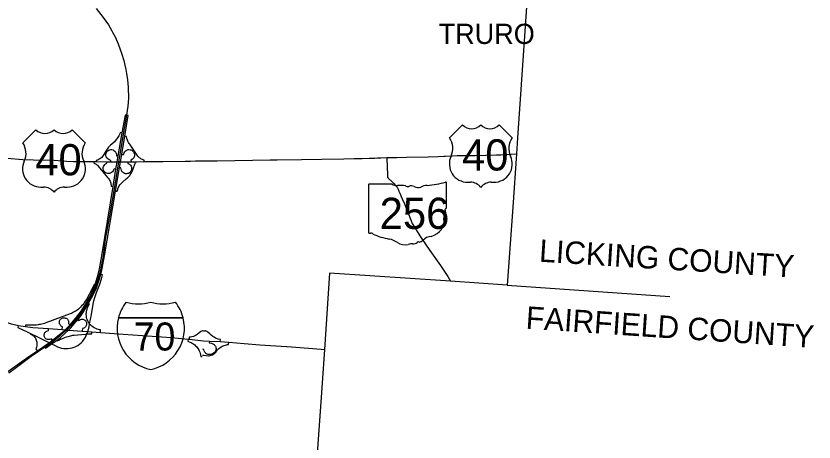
# Model space of a CAD drawing. Extents: x -1146 to -445, y -1283 to -822.
# Drawn here: x -786.6 to -697.7, y -1096.4 to -1048.9 of the extents above; entities that cross this region are included whole.
import ezdxf

# ---------------------------------------------------------------- set-up
doc = ezdxf.new("R2010")
doc.units = 0
for name, color, linetype in [('GM_X_Adjacent_County', 7, 'Continuous'), ('GM_X_Adjacent_County_Text', 7, 'Continuous'), ('GM_X_County', 7, 'Continuous'), ('GM_X_Interchange_Ramps', 7, 'Continuous'), ('GM_X_Interstate_Route', 7, 'Continuous'), ('GM_X_Interstate_Shield', 7, 'Continuous'), ('GM_X_State_Route', 7, 'Continuous'), ('GM_X_State_Shield', 7, 'Continuous'), ('GM_X_Township_Text', 7, 'Continuous'), ('GM_X_US_Route', 7, 'Continuous'), ('GM_X_US_Shield', 7, 'Continuous')]:
    doc.layers.add(name, color=color, linetype=linetype)

msp = doc.modelspace()

# ---------------------------------------------------------------- linework, layer by layer
at = {"layer": 'GM_X_Adjacent_County'}
msp.add_line((-731.874, -1078.923), (-713.764, -1080.18), dxfattribs=at)
at = {"layer": 'GM_X_County'}
msp.add_lwpolyline([(-722.786, -1003.387), (-723.025, -1007.4), (-723.916, -1019.919), (-723.932, -1020.299), (-724.826, -1035.597), (-725.049, -1038.96), (-725.51, -1045.915), (-729.553, -1045.554), (-729.679, -1047.366), (-730.581, -1060.332), (-730.732, -1062.497), (-730.857, -1064.3), (-731.27, -1070.236), (-731.413, -1072.292), (-731.874, -1078.923), (-738.201, -1078.491), (-751.672, -1077.572), (-752.243, -1086.092), (-752.566, -1090.897), (-753.436, -1103.447)], dxfattribs=at)
at = {"layer": 'GM_X_Interchange_Ramps'}
for points in [[(-774.284, -1059.994), (-774.439, -1059.969), (-774.786, -1061.933), (-775.242, -1064.513), (-775.362, -1065.189), (-775.49, -1065.978), (-775.805, -1067.922), (-777.062, -1075.666), (-777.33, -1077.117), (-777.534, -1078.031), (-777.805, -1078.876), (-777.93, -1079.239), (-778.251, -1079.987), (-778.835, -1081.021), (-779.33, -1081.793), (-779.991, -1082.661), (-780.581, -1083.362), (-780.665, -1083.461), (-781.112, -1083.913), (-781.367, -1084.17), (-782.298, -1084.92), (-782.503, -1085.083), (-782.853, -1085.362), (-782.864, -1085.37), (-784.195, -1086.275), (-785.164, -1086.934), (-787.48, -1088.581)], [(-783.374, -1085.85), (-783.3, -1085.951), (-782.615, -1085.478), (-782.329, -1085.281), (-782.009, -1085.06), (-781.629, -1084.755), (-781.096, -1084.295), (-780.73, -1083.942), (-780.464, -1083.685), (-779.903, -1083.025), (-779.713, -1082.782), (-779.342, -1082.309), (-778.714, -1081.34), (-778.5, -1080.957), (-778.304, -1080.606), (-778.007, -1080.071), (-777.672, -1079.337), (-777.353, -1078.448), (-777.14, -1077.724), (-777.003, -1077.052), (-776.733, -1075.67), (-775.493, -1068.432), (-775.046, -1065.819), (-774.938, -1065.189), (-774.937, -1065.183), (-774.801, -1064.35), (-774.468, -1062.312), (-774.095, -1060.023), (-774.284, -1059.994)], [(-774.786, -1061.933), (-774.968, -1061.904), (-775.036, -1062.069), (-775.092, -1062.19), (-775.148, -1062.296), (-775.205, -1062.396), (-775.269, -1062.496), (-775.343, -1062.602), (-775.418, -1062.701), (-775.502, -1062.801), (-775.55, -1062.855), (-775.622, -1062.93), (-775.915, -1063.2), (-776.052, -1063.32), (-776.163, -1063.429), (-776.265, -1063.541), (-776.346, -1063.64), (-776.431, -1063.755), (-776.508, -1063.87), (-776.574, -1063.981), (-776.798, -1064.378), (-776.865, -1064.485), (-776.944, -1064.587), (-777.035, -1064.683), (-777.146, -1064.778), (-777.239, -1064.843), (-777.322, -1064.891), (-777.415, -1064.937), (-777.518, -1064.976), (-777.643, -1065.013), (-777.647, -1065.151)], [(-772.304, -1065.152), (-772.308, -1064.992), (-772.408, -1064.962), (-772.508, -1064.925), (-772.601, -1064.882), (-772.685, -1064.834), (-772.767, -1064.78), (-772.844, -1064.721), (-772.916, -1064.657), (-772.976, -1064.596), (-773.028, -1064.536), (-773.921, -1063.217), (-773.992, -1063.116), (-774.053, -1063.015), (-774.092, -1062.941), (-774.13, -1062.858), (-774.167, -1062.765), (-774.2, -1062.669), (-774.229, -1062.56), (-774.271, -1062.342), (-774.468, -1062.312)], [(-776.014, -1065.178), (-776.01, -1065.018), (-776.191, -1064.95), (-776.35, -1064.859), (-776.485, -1064.715), (-776.544, -1064.573), (-776.567, -1064.449), (-776.564, -1064.329), (-776.533, -1064.201), (-776.491, -1064.112), (-776.415, -1064.007), (-776.339, -1063.938), (-776.243, -1063.877), (-776.142, -1063.838), (-776.024, -1063.817), (-775.899, -1063.821), (-775.761, -1063.858), (-775.67, -1063.904), (-775.575, -1063.976), (-775.501, -1064.062), (-775.449, -1064.15), (-775.414, -1064.241), (-775.397, -1064.321), (-775.379, -1064.492), (-775.242, -1064.513)], [(-774.801, -1064.35), (-774.627, -1064.377), (-774.574, -1064.253), (-774.48, -1064.074), (-774.422, -1064.002), (-774.324, -1063.918), (-774.243, -1063.871), (-774.157, -1063.838), (-774.079, -1063.82), (-773.999, -1063.813), (-773.883, -1063.822), (-773.77, -1063.853), (-773.694, -1063.889), (-773.627, -1063.932), (-773.556, -1063.995), (-773.494, -1064.071), (-773.45, -1064.144), (-773.414, -1064.236), (-773.393, -1064.328), (-773.388, -1064.417), (-773.397, -1064.516), (-773.429, -1064.63), (-773.478, -1064.727), (-773.547, -1064.818), (-773.61, -1064.876), (-773.777, -1064.991), (-773.771, -1065.173)], [(-777.922, -1065.146), (-777.926, -1065.307), (-777.794, -1065.367), (-777.715, -1065.411), (-777.654, -1065.45), (-777.588, -1065.5), (-777.514, -1065.563), (-777.438, -1065.643), (-776.377, -1066.917), (-776.289, -1067.028), (-776.222, -1067.129), (-776.161, -1067.236), (-776.112, -1067.338), (-776.072, -1067.439), (-776.036, -1067.548), (-776.008, -1067.657), (-775.989, -1067.757), (-775.973, -1067.893), (-775.805, -1067.922)], [(-775.49, -1065.978), (-775.643, -1065.955), (-775.774, -1066.185), (-775.85, -1066.275), (-775.932, -1066.356), (-776.044, -1066.428), (-776.164, -1066.47), (-776.288, -1066.485), (-776.408, -1066.475), (-776.532, -1066.435), (-776.635, -1066.377), (-776.724, -1066.297), (-776.793, -1066.205), (-776.846, -1066.09), (-776.873, -1065.969), (-776.87, -1065.817), (-776.836, -1065.694), (-776.777, -1065.581), (-776.695, -1065.484), (-776.606, -1065.415), (-776.474, -1065.343), (-776.47, -1065.171)], [(-775.493, -1068.432), (-775.309, -1068.464), (-775.257, -1068.271), (-775.224, -1068.174), (-775.187, -1068.08), (-775.138, -1067.976), (-775.075, -1067.865), (-775.003, -1067.754), (-774.937, -1067.667), (-774.844, -1067.56), (-774.733, -1067.452), (-774.679, -1067.405), (-774.3, -1067.082), (-774.209, -1067.006), (-774.128, -1066.932), (-774.055, -1066.859), (-773.989, -1066.785), (-773.921, -1066.703), (-773.852, -1066.609), (-773.791, -1066.518), (-773.732, -1066.42), (-773.607, -1066.172), (-773.52, -1065.947), (-773.363, -1065.434), (-773.329, -1065.346), (-773.275, -1065.276), (-773.192, -1065.219), (-773.194, -1065.165)], [(-774.124, -1065.178), (-774.119, -1065.353), (-773.928, -1065.452), (-773.841, -1065.54), (-773.768, -1065.649), (-773.721, -1065.772), (-773.704, -1065.883), (-773.708, -1065.998), (-773.746, -1066.138), (-773.803, -1066.248), (-773.882, -1066.342), (-773.958, -1066.404), (-774.066, -1066.463), (-774.166, -1066.494), (-774.274, -1066.508), (-774.38, -1066.501), (-774.501, -1066.47), (-774.614, -1066.413), (-774.7, -1066.344), (-774.758, -1066.28), (-774.81, -1066.2), (-774.843, -1066.127), (-774.876, -1065.996), (-774.898, -1065.84), (-775.046, -1065.819)], [(-786.324, -1083.405), (-786.378, -1083.656), (-785.347, -1084.128), (-784.972, -1084.305), (-784.257, -1084.641), (-783.082, -1085.25), (-782.853, -1085.362), (-782.73, -1085.422), (-782.615, -1085.478), (-782.22, -1085.67), (-781.962, -1085.8), (-781.733, -1085.885), (-781.508, -1085.945), (-781.252, -1085.986), (-781.008, -1086), (-780.808, -1085.993), (-780.547, -1085.958), (-780.313, -1085.903), (-780.107, -1085.833), (-779.91, -1085.747), (-779.711, -1085.637), (-779.513, -1085.501), (-779.33, -1085.348), (-779.174, -1085.189), (-778.992, -1084.96), (-778.854, -1084.74), (-778.759, -1084.551), (-778.683, -1084.365), (-778.633, -1084.246), (-778.581, -1084.097), (-778.576, -1084.083), (-778.506, -1083.845), (-778.443, -1083.561), (-778.382, -1083.247), (-778.175, -1082.182), (-777.983, -1081.038), (-777.897, -1080.663), (-777.812, -1080.3), (-777.619, -1079.733), (-777.256, -1078.803), (-777.064, -1078.215), (-776.943, -1077.778), (-777.14, -1077.724)], [(-777.805, -1078.876), (-777.887, -1078.846), (-778.175, -1079.466), (-778.432, -1079.979), (-778.699, -1080.46), (-778.945, -1080.835), (-779.029, -1080.953), (-779.151, -1081.109), (-779.271, -1081.246), (-779.397, -1081.376), (-779.518, -1081.49), (-779.628, -1081.584), (-779.773, -1081.698), (-779.884, -1081.777), (-780.012, -1081.86), (-780.164, -1081.949), (-780.276, -1082.009), (-780.407, -1082.072), (-780.538, -1082.128), (-783.252, -1083.133), (-783.408, -1083.183), (-783.545, -1083.222), (-783.715, -1083.263), (-783.872, -1083.296), (-784.005, -1083.319), (-784.105, -1083.34), (-784.298, -1083.368), (-784.452, -1083.387), (-784.842, -1083.401), (-785.517, -1083.368), (-785.536, -1083.537)], [(-777.173, -1084.185), (-777.154, -1083.921), (-777.167, -1083.918), (-777.292, -1083.892), (-777.395, -1083.866), (-777.532, -1083.826), (-777.688, -1083.77), (-777.872, -1083.682), (-778.002, -1083.602), (-778.129, -1083.508), (-778.249, -1083.4), (-778.325, -1083.319), (-778.382, -1083.247), (-778.456, -1083.151), (-778.525, -1083.043), (-778.591, -1082.917), (-778.648, -1082.783), (-778.688, -1082.662), (-778.721, -1082.533), (-778.748, -1082.358), (-778.757, -1082.215), (-778.755, -1082.094), (-778.745, -1081.972), (-778.72, -1081.82), (-778.692, -1081.711), (-778.653, -1081.584), (-778.612, -1081.469), (-778.552, -1081.32), (-778.484, -1081.172), (-778.402, -1081.011), (-778.5, -1080.957)], [(-781.432, -1083.885), (-781.413, -1083.566), (-781.433, -1083.557), (-781.492, -1083.523), (-781.537, -1083.492), (-781.588, -1083.45), (-781.634, -1083.401), (-781.675, -1083.344), (-781.707, -1083.283), (-781.726, -1083.236), (-781.743, -1083.171), (-781.751, -1083.111), (-781.751, -1083.028), (-781.741, -1082.964), (-781.722, -1082.897), (-781.685, -1082.817), (-781.646, -1082.758), (-781.608, -1082.714), (-781.559, -1082.669), (-781.503, -1082.63), (-781.444, -1082.599), (-781.375, -1082.575), (-781.311, -1082.561), (-781.234, -1082.556), (-781.14, -1082.565), (-781.06, -1082.587), (-780.995, -1082.616), (-780.925, -1082.66), (-780.865, -1082.713), (-780.816, -1082.773), (-780.779, -1082.833), (-780.753, -1082.892), (-780.731, -1082.968), (-780.721, -1083.042), (-780.722, -1083.115), (-780.735, -1083.2), (-780.581, -1083.362)], [(-779.713, -1082.782), (-779.608, -1082.861), (-779.536, -1082.81), (-779.445, -1082.76), (-779.376, -1082.737), (-779.299, -1082.723), (-779.224, -1082.72), (-779.142, -1082.73), (-779.044, -1082.76), (-778.982, -1082.791), (-778.914, -1082.838), (-778.858, -1082.891), (-778.817, -1082.942), (-778.771, -1083.022), (-778.741, -1083.105), (-778.725, -1083.193), (-778.724, -1083.268), (-778.737, -1083.361), (-778.758, -1083.429), (-778.787, -1083.491), (-778.837, -1083.566), (-778.895, -1083.627), (-778.962, -1083.678), (-779.028, -1083.715), (-779.19, -1083.77), (-779.212, -1084.05)], [(-784.972, -1084.305), (-784.99, -1084.343), (-784.889, -1084.392), (-784.774, -1084.462), (-784.664, -1084.548), (-784.556, -1084.656), (-784.477, -1084.756), (-784.417, -1084.848), (-784.372, -1084.933), (-784.323, -1085.046), (-784.286, -1085.165), (-784.263, -1085.278), (-784.251, -1085.387), (-784.248, -1085.475), (-784.254, -1085.595), (-784.27, -1085.703), (-784.304, -1085.836), (-784.376, -1086.029), (-784.195, -1086.275)], [(-782.503, -1085.083), (-782.621, -1084.921), (-782.7, -1084.95), (-782.802, -1084.977), (-782.892, -1084.992), (-782.982, -1084.997), (-783.083, -1084.98), (-783.17, -1084.947), (-783.243, -1084.903), (-783.317, -1084.836), (-783.373, -1084.762), (-783.404, -1084.702), (-783.435, -1084.602), (-783.445, -1084.528), (-783.44, -1084.434), (-783.426, -1084.368), (-783.395, -1084.286), (-783.356, -1084.221), (-783.301, -1084.154), (-783.231, -1084.096), (-783.16, -1084.055), (-782.971, -1083.985), (-782.961, -1083.754)], [(-782.009, -1085.06), (-781.952, -1085.138), (-781.741, -1085.025), (-781.614, -1084.961), (-781.467, -1084.892), (-781.34, -1084.837), (-781.143, -1084.76), (-780.946, -1084.691), (-780.79, -1084.643), (-780.637, -1084.601), (-780.505, -1084.568), (-780.359, -1084.536), (-780.256, -1084.516), (-780.088, -1084.489), (-778.848, -1084.374), (-778.683, -1084.365), (-778.523, -1084.357), (-778.171, -1084.348), (-778.146, -1084.349), (-778.129, -1084.125)], [(-765.618, -1084.044), (-765.73, -1084.029), (-765.815, -1084.029), (-765.882, -1084.045), (-765.986, -1084.098), (-766.206, -1084.287), (-766.395, -1084.433), (-766.513, -1084.503), (-766.65, -1084.569), (-766.828, -1084.638), (-767.013, -1084.69), (-767.157, -1084.725), (-767.281, -1084.74), (-767.302, -1084.955)], [(-763.828, -1085.214), (-763.811, -1084.978), (-764.077, -1084.93), (-764.235, -1084.882), (-764.362, -1084.822), (-764.511, -1084.739), (-764.653, -1084.639), (-764.837, -1084.492), (-764.986, -1084.359), (-765.214, -1084.152), (-765.31, -1084.085), (-765.386, -1084.043), (-765.468, -1084.015), (-765.513, -1084.018), (-765.556, -1084.038), (-765.618, -1084.044)], [(-767.425, -1084.947), (-767.448, -1085.178), (-767.287, -1085.23), (-767.18, -1085.273), (-767.075, -1085.322), (-766.976, -1085.376), (-766.871, -1085.441), (-766.777, -1085.507), (-766.676, -1085.589), (-766.574, -1085.684), (-766.496, -1085.767), (-766.411, -1085.868), (-766.318, -1085.998), (-766.238, -1086.132), (-766.176, -1086.255), (-766.114, -1086.406), (-766.069, -1086.547), (-766.033, -1086.699), (-765.989, -1086.878), (-765.831, -1086.889)], [(-765.046, -1085.157), (-765.053, -1085.366), (-764.803, -1085.408), (-764.721, -1085.434), (-764.651, -1085.465), (-764.588, -1085.503), (-764.529, -1085.548), (-764.468, -1085.606), (-764.421, -1085.663), (-764.374, -1085.737), (-764.341, -1085.804), (-764.313, -1085.885), (-764.3, -1085.971), (-764.301, -1086.062), (-764.317, -1086.164), (-764.364, -1086.287), (-764.418, -1086.373), (-764.492, -1086.445), (-764.584, -1086.511), (-764.687, -1086.569), (-764.785, -1086.611), (-764.884, -1086.642), (-765.011, -1086.665), (-765.127, -1086.661), (-765.216, -1086.642), (-765.349, -1086.584), (-765.424, -1086.533), (-765.496, -1086.464), (-765.552, -1086.389), (-765.585, -1086.33), (-765.62, -1086.255), (-765.671, -1086.084), (-765.763, -1086.078)], [(-765.818, -1086.74), (-765.702, -1086.748), (-765.388, -1086.774), (-765.154, -1086.792), (-765.065, -1086.794), (-764.695, -1086.703), (-764.312, -1086.395), (-764.181, -1086.167), (-764.084, -1086.064), (-763.991, -1085.979), (-763.891, -1085.9), (-763.75, -1085.805), (-763.621, -1085.734), (-763.508, -1085.683), (-763.389, -1085.639), (-763.253, -1085.599), (-763.129, -1085.573), (-763.036, -1085.559), (-762.912, -1085.541), (-762.894, -1085.288)]]:
    msp.add_lwpolyline(points, dxfattribs=at)
at = {"layer": 'GM_X_Interstate_Route'}
for points in [[(-777.65, -1048.076), (-776.881, -1049.072), (-776.292, -1049.891), (-775.908, -1050.57), (-775.838, -1050.706)], [(-775.838, -1050.706), (-775.55, -1051.261), (-775.197, -1052.024)], [(-775.197, -1052.024), (-775.154, -1052.118), (-774.821, -1053.052), (-774.578, -1053.872), (-774.45, -1054.396), (-774.335, -1054.883), (-774.258, -1055.343), (-774.169, -1056.022), (-774.092, -1056.841), (-774.066, -1058.082), (-774.129, -1059), (-774.16, -1059.204)], [(-774.16, -1059.204), (-774.235, -1059.715), (-774.238, -1059.731)], [(-774.284, -1059.994), (-774.672, -1062.321), (-774.92, -1063.699), (-775.171, -1065.193)], [(-774.238, -1059.731), (-774.284, -1059.994)], [(-775.171, -1065.193), (-775.617, -1067.957), (-776.08, -1070.774), (-776.645, -1073.808), (-776.886, -1075.666), (-777.169, -1077.246), (-777.451, -1078.333), (-777.843, -1079.356), (-778.321, -1080.4), (-779.115, -1081.699), (-779.615, -1082.412), (-780.294, -1083.227), (-780.946, -1083.927)], [(-799.319, -1081.382), (-799.261, -1081.376), (-798.675, -1081.307), (-797.175, -1081.124), (-796.666, -1081.08), (-796.073, -1081.06), (-795.372, -1081.063), (-794.743, -1081.098), (-794.179, -1081.164), (-793.553, -1081.245), (-793.167, -1081.306), (-792.65, -1081.411), (-792.083, -1081.547), (-791.298, -1081.781), (-790.473, -1082.074), (-788.306, -1082.814), (-787.138, -1083.227), (-786.587, -1083.349), (-786.463, -1083.375)], [(-786.463, -1083.375), (-786.324, -1083.405), (-785.536, -1083.537), (-784.72, -1083.63), (-782.961, -1083.754)], [(-780.946, -1083.927), (-781.322, -1084.255), (-782.082, -1084.913), (-782.73, -1085.422), (-782.74, -1085.43), (-783.374, -1085.85)], [(-782.961, -1083.754), (-781.432, -1083.885), (-781.112, -1083.913), (-780.946, -1083.927)], [(-780.946, -1083.927), (-780.73, -1083.942), (-779.212, -1084.05), (-778.581, -1084.097), (-778.571, -1084.097), (-778.129, -1084.125)], [(-778.129, -1084.125), (-778.129, -1084.125), (-777.173, -1084.185)], [(-777.173, -1084.185), (-774.637, -1084.399), (-769.26, -1084.775), (-767.425, -1084.947), (-767.302, -1084.955), (-765.687, -1085.114), (-765.046, -1085.157)], [(-765.046, -1085.157), (-763.828, -1085.214), (-762.894, -1085.288), (-761.174, -1085.429), (-761.164, -1085.429)], [(-783.374, -1085.85), (-783.374, -1085.85), (-784.67, -1086.718), (-784.901, -1086.891)], [(-761.164, -1085.429), (-759.416, -1085.574), (-756.451, -1085.775), (-756.37, -1085.78)], [(-756.37, -1085.78), (-755.414, -1085.845), (-752.607, -1086.066), (-752.243, -1086.093)], [(-784.901, -1086.891), (-786.657, -1088.203), (-787.369, -1088.733)]]:
    msp.add_lwpolyline(points, dxfattribs=at)
at = {"layer": 'GM_X_Interstate_Shield'}
for p, q in [((-775.181, -1082.579), (-767.968, -1082.579)), ((-767.968, -1082.579), (-775.181, -1082.579)), ((-767.968, -1082.579), (-775.181, -1082.579))]:
    msp.add_line(p, q, dxfattribs=at)
for centre, start, end in [((-770.637, -1083.728), 141.66896, 165.80665), ((-772.944, -1076.338), 253.00908, 286.99093), ((-770.205, -1076.338), 253.00908, 286.99093), ((-772.512, -1083.728), 14.19335, 38.33104), ((-770.637, -1083.728), 165.80665, 258.46304), ((-772.512, -1083.728), 281.53696, 14.19335)]:
    msp.add_arc(centre, 4.688, start, end, dxfattribs=at)
at = {"layer": 'GM_X_State_Route'}
for points in [[(-745.282, -1064.712), (-745.27, -1065.174), (-745.262, -1065.368)], [(-745.262, -1065.368), (-745.242, -1065.881), (-745.222, -1066.447), (-745.21, -1066.782), (-745.193, -1066.873), (-745.162, -1066.932)], [(-745.162, -1066.932), (-745.15, -1066.954), (-745.123, -1066.984), (-744.708, -1067.404)], [(-744.708, -1067.404), (-744.543, -1067.57), (-744.301, -1067.824), (-744.135, -1068.007), (-744.032, -1068.218), (-743.936, -1068.444)], [(-743.936, -1068.444), (-743.833, -1068.686), (-743.734, -1068.928)], [(-743.734, -1068.928), (-743.721, -1068.958), (-743.583, -1069.29), (-743.327, -1069.873), (-742.573, -1071.77), (-742.452, -1072.045), (-742.332, -1072.267), (-742.034, -1072.76)], [(-742.034, -1072.76), (-741.626, -1073.433)], [(-741.626, -1073.433), (-741.462, -1073.654), (-740.505, -1075.045), (-739.295, -1076.739), (-738.497, -1077.959), (-738.201, -1078.491)]]:
    msp.add_lwpolyline(points, dxfattribs=at)
at = {"layer": 'GM_X_State_Shield'}
for p, q in [((-747.34, -1067.748), (-747.34, -1073.031)), ((-744.707, -1067.657), (-747.255, -1067.657)), ((-738.639, -1070.29), (-738.639, -1067.526)), ((-738.64, -1070.29), (-738.639, -1070.29))]:
    msp.add_line(p, q, dxfattribs=at)
for centre, major_axis, start_param, end_param in [((-747.241, -1067.737), (0.101, 0), 1.712693, 3.28349), ((-744.1, -1067.044), (0.978, 0), 4.042523, 4.731795), ((-743.776, -1070.623), (3.51, 0), 1.404758, 1.657858), ((-742.979, -1067.71), (0.282, 0), 3.836095, 5.185415), ((-742.565, -1068.32), (0.586, 0), 0.950623, 2.079405), ((-741.808, -1067.483), (0.705, 0), 4.081561, 5.145723), ((-740.562, -1069.271), (1.856, 0), 1.699011, 2.107814), ((-741.739, -1060.455), (9.227, 0), 4.814394, 5.042369), ((-738.736, -1067.515), (0.0969, 0), 6.141152, 7.989035), ((-738.662, -1070.493), (0.15, 0), 1.883978, 3.671073), ((-739.616, -1070.842), (0.9, 0), 5.934695, 6.695948), ((-738.743, -1070.301), (0.104, 0), 5.05454, 6.418171), ((-741.222, -1071.798), (2.308, 0), 5.101752, 6.440018), ((-738.292, -1071.447), (0.655, 0), 2.387724, 3.262537), ((-747.24, -1073.043), (0.102, 0), 3.00124, 4.508301), ((-747.224, -1072.503), (0.776, 0), 4.665946, 4.897461), ((-747.066, -1073.336), (0.28, 0), 0.519207, 1.627899), ((-743.533, -1068.59), (6.663, 0), 4.195997, 4.488961), ((-740.249, -1074.515), (1.264, 0), 1.647645, 2.488434), ((-745.519, -1075.405), (2.085, 0), 0.823519, 1.323587), ((-743.264, -1073.363), (1.323, 0), 4.026481, 4.996735), ((-742.5, -1075.189), (1.087, 0), 1.495662, 1.94098), ((-742.403, -1073.758), (0.705, 0), 4.691044, 5.507374), ((-741.766, -1074.27), (0.198, 0), 1.147584, 2.315152), ((-741.85, -1073.544), (0.746, 0), 4.937069, 5.64225)]:
    msp.add_ellipse(centre, major_axis=major_axis, ratio=0.8, start_param=start_param, end_param=end_param, dxfattribs=at)
at = {"layer": 'GM_X_US_Route'}
for points in [[(-792.147, -1064.59), (-791.202, -1064.629), (-787.566, -1064.782), (-785.822, -1064.934), (-784.628, -1064.953), (-782.338, -1064.99), (-780.946, -1065.094)], [(-747.146, -1064.776), (-746.623, -1064.752)], [(-746.623, -1064.752), (-746.324, -1064.738), (-745.969, -1064.723), (-745.282, -1064.712), (-744.178, -1064.679), (-743.112, -1064.657), (-740.676, -1064.602), (-739.564, -1064.574), (-738.927, -1064.548)], [(-738.927, -1064.548), (-738.868, -1064.546), (-738.793, -1064.543)], [(-738.793, -1064.543), (-737.986, -1064.51)], [(-737.986, -1064.51), (-737.448, -1064.488)], [(-737.448, -1064.488), (-737.397, -1064.486), (-735.685, -1064.463), (-735.481, -1064.458), (-735.43, -1064.457)], [(-735.43, -1064.457), (-734.255, -1064.43), (-734.219, -1064.429)], [(-734.219, -1064.429), (-733.066, -1064.403), (-733.056, -1064.403), (-732.622, -1064.382), (-732.605, -1064.382)], [(-732.605, -1064.382), (-730.857, -1064.3)], [(-780.946, -1065.094), (-780.178, -1065.152), (-779.614, -1065.144)], [(-779.614, -1065.144), (-778.941, -1065.135), (-777.922, -1065.146), (-777.647, -1065.151), (-776.47, -1065.171), (-776.014, -1065.178), (-775.362, -1065.189), (-775.171, -1065.193)], [(-775.171, -1065.193), (-774.938, -1065.189), (-774.124, -1065.178), (-773.771, -1065.173), (-773.194, -1065.165), (-772.304, -1065.152), (-771.37, -1065.145)], [(-771.37, -1065.145), (-771.02, -1065.142), (-770.289, -1065.153), (-770.217, -1065.151)], [(-770.217, -1065.151), (-767.74, -1065.108), (-767.672, -1065.107)], [(-767.672, -1065.107), (-767.189, -1065.099), (-767.137, -1065.098)], [(-767.137, -1065.098), (-766.601, -1065.083)], [(-766.601, -1065.083), (-766.333, -1065.075)], [(-766.333, -1065.075), (-766.113, -1065.069), (-766.066, -1065.068)], [(-766.066, -1065.068), (-765.696, -1065.06), (-765.53, -1065.06)], [(-765.53, -1065.06), (-764.271, -1065.067), (-764.191, -1065.072), (-758.277, -1064.96), (-757.483, -1064.949), (-754.777, -1064.901), (-752.537, -1064.889), (-752.522, -1064.888), (-750.059, -1064.838), (-748.93, -1064.815), (-748.014, -1064.796), (-747.245, -1064.78), (-747.146, -1064.776)]]:
    msp.add_lwpolyline(points, dxfattribs=at)
at = {"layer": 'GM_X_US_Shield'}
for p, q in [((-736.848, -1061.07), (-738.299, -1062.52)), ((-731.338, -1062.52), (-732.788, -1061.07)), ((-784.379, -1061.609), (-785.829, -1063.059)), ((-778.868, -1063.059), (-780.319, -1061.609)), ((-783.799, -1067.99), (-783.509, -1067.99)), ((-781.189, -1067.99), (-780.899, -1067.99)), ((-736.268, -1067.451), (-735.978, -1067.451)), ((-733.658, -1067.451), (-733.368, -1067.451))]:
    msp.add_line(p, q, dxfattribs=at)
for centre, radius, start, end in [((-735.833, -1060.034), 1.45, 225.573, 314.427), ((-733.803, -1060.034), 1.45, 225.573, 314.427), ((-783.364, -1060.573), 1.45, 225.573, 314.427), ((-781.334, -1060.573), 1.45, 225.573, 314.427), ((-739.962, -1063.684), 2.03, 334.54712, 35.00093), ((-729.674, -1063.684), 2.03, 144.99907, 205.45288), ((-787.493, -1064.223), 2.03, 334.54712, 35.00093), ((-777.205, -1064.223), 2.03, 144.99907, 205.45288), ((-736.291, -1065.42), 2.03, 154.83192, 270.63826), ((-733.345, -1065.42), 2.03, 269.36174, 25.16808), ((-783.822, -1065.959), 2.03, 154.83192, 270.63826), ((-780.876, -1065.959), 2.03, 269.36174, 25.16808), ((-783.509, -1069.44), 1.45, 36.8699, 90), ((-781.189, -1069.44), 1.45, 90, 143.1301), ((-735.978, -1068.901), 1.45, 36.8699, 90), ((-733.658, -1068.901), 1.45, 90, 143.1301)]:
    msp.add_arc(centre, radius, start, end, dxfattribs=at)

# ---------------------------------------------------------------- texts
at = {"layer": 'GM_X_Adjacent_County_Text'}
for s, rotation, p in [('LICKING COUNTY', 356.4293, (-728.369, -1076.306)), ('FAIRFIELD COUNTY', 356.16459, (-729.863, -1083.769))]:
    msp.add_text(s, height=2.5, rotation=rotation, dxfattribs=at).set_placement(p)
at = {"layer": 'GM_X_Interstate_Shield'}
msp.add_text('70', height=3.125, dxfattribs=at).set_placement((-773.481, -1086.212))
at = {"layer": 'GM_X_State_Shield'}
msp.add_text('256', height=3.4805, dxfattribs=at).set_placement((-746.085, -1072.659))
at = {"layer": 'GM_X_Township_Text'}
msp.add_text('TRURO', height=2.25, rotation=0.00001, dxfattribs=at).set_placement((-739.506, -1052.037))
at = {"layer": 'GM_X_US_Shield'}
for p in [(-736.909, -1066.145), (-784.44, -1066.684)]:
    msp.add_text('40', height=3.4805, dxfattribs=at).set_placement(p)

doc.saveas('drawing.dxf')
